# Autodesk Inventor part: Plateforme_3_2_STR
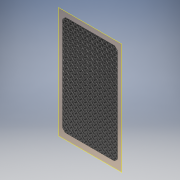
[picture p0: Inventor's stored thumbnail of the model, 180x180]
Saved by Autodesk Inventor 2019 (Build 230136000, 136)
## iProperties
Created: 2018-07
Part Number: Plateforme_3_2_STR
Material: Générique
Document SubType Name: Modeling
Designer: Fabian Perrée
Density: 1 g/cm^3
Appearance: Par défaut
Author: Fabian Perrée
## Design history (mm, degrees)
node "Plan de construction1"
sketch "Esquisse1"
  geometry: L1 (1000, 250)-(0, 250) reference; L2 (0, -1500)-(0, 250) reference; L3 (1000, -1500)-(0, -1500) reference; L4 (1000, -1500)-(1000, 250) reference; L5 (45, -1455)-(45, 205); L6 (45, 205)-(955, 205); L7 (955, 205)-(955, -1455); L8 (955, -1455)-(45, -1455)
  constraints: 8 end point, 3 other
  dimensions: "d8" = 45 distance between parallel lines of L3 L8
extrude "Extrusion1" new body sketch "Esquisse1" distance "d0" = 5; taper "d1" = 0 deg
node "Solide1"
node "Référence12"
